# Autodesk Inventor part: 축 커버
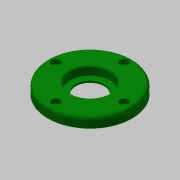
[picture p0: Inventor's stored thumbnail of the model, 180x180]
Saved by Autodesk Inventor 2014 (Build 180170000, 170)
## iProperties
Created: 2015-10
Part Number: 축 커버
Document SubType Name: Modeling
Designer: mdu
Density: 1 g/cm^3
Material: 일반
Appearance: 진녹색
Mass: 40.896 g
Surface Area: 134.096 cm^2
Volume: 40.896 cm^3
Author: mdu
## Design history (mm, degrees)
sketch "스케치1"
  geometry: C1 r 40 at (0, 0) reference; C2 r 26 at (0, 0) reference; 1 further point
  node "참조1"
  node "참조2"
extrude "돌출1" new body sketch "스케치1" distance "d0" = 10; taper "d1" = 0 deg
extrude "돌출2" join sketch "스케치1" distance "d2" = 3; taper "d3" = 0 deg
hole "구멍1" diameter "d6" = 27; stored, may be unused: countersink angle "d10" = 90 deg, drill point angle "d12" = 118 deg; dims "d7" = 6, "d8" = 38, "d9" = 8.3, "d11" = 8, "d33" = 10, "d34" = 10
sketch "스케치2"
  geometry: C1 r 20 at (0, 0); 1 further point
  constraints: 1 centre point, 1 coincident
  dimensions: "d13" = 40 diameter of C1
extrude "돌출3" cut sketch "스케치2" distance "d14" = 3; taper "d15" = 0 deg
sketch "스케치3"
  geometry: C1 r 1.621 at (0, 32.5) reference; 1 further point
hole "구멍2" sketch "스케치3" at (0, 32.5) diameter "d16" = 4.5; stored, may be unused: countersink angle "d20" = 90 deg, drill point angle "d22" = 118 deg; dims "d17" = 6, "d18" = 8, "d19" = 4.4, "d21" = 8
fillet "모깎기1" dims "d26" = 3, "d27" = 0.3
chamfer "모따기1" distance "d28" = 1; stored, may be unused: second distance "d29" = 2, angle "d30" = 45 deg
chamfer "모따기2" distance "d31" = 0.8; stored, may be unused: second distance "d32" = 2, angle "d35" = 30 deg
node "솔리드1"
pattern_circular "원형 패턴1" dims angle "d24" = 360 deg
node "참조3"
